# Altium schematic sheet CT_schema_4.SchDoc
size 349 x 342 mm
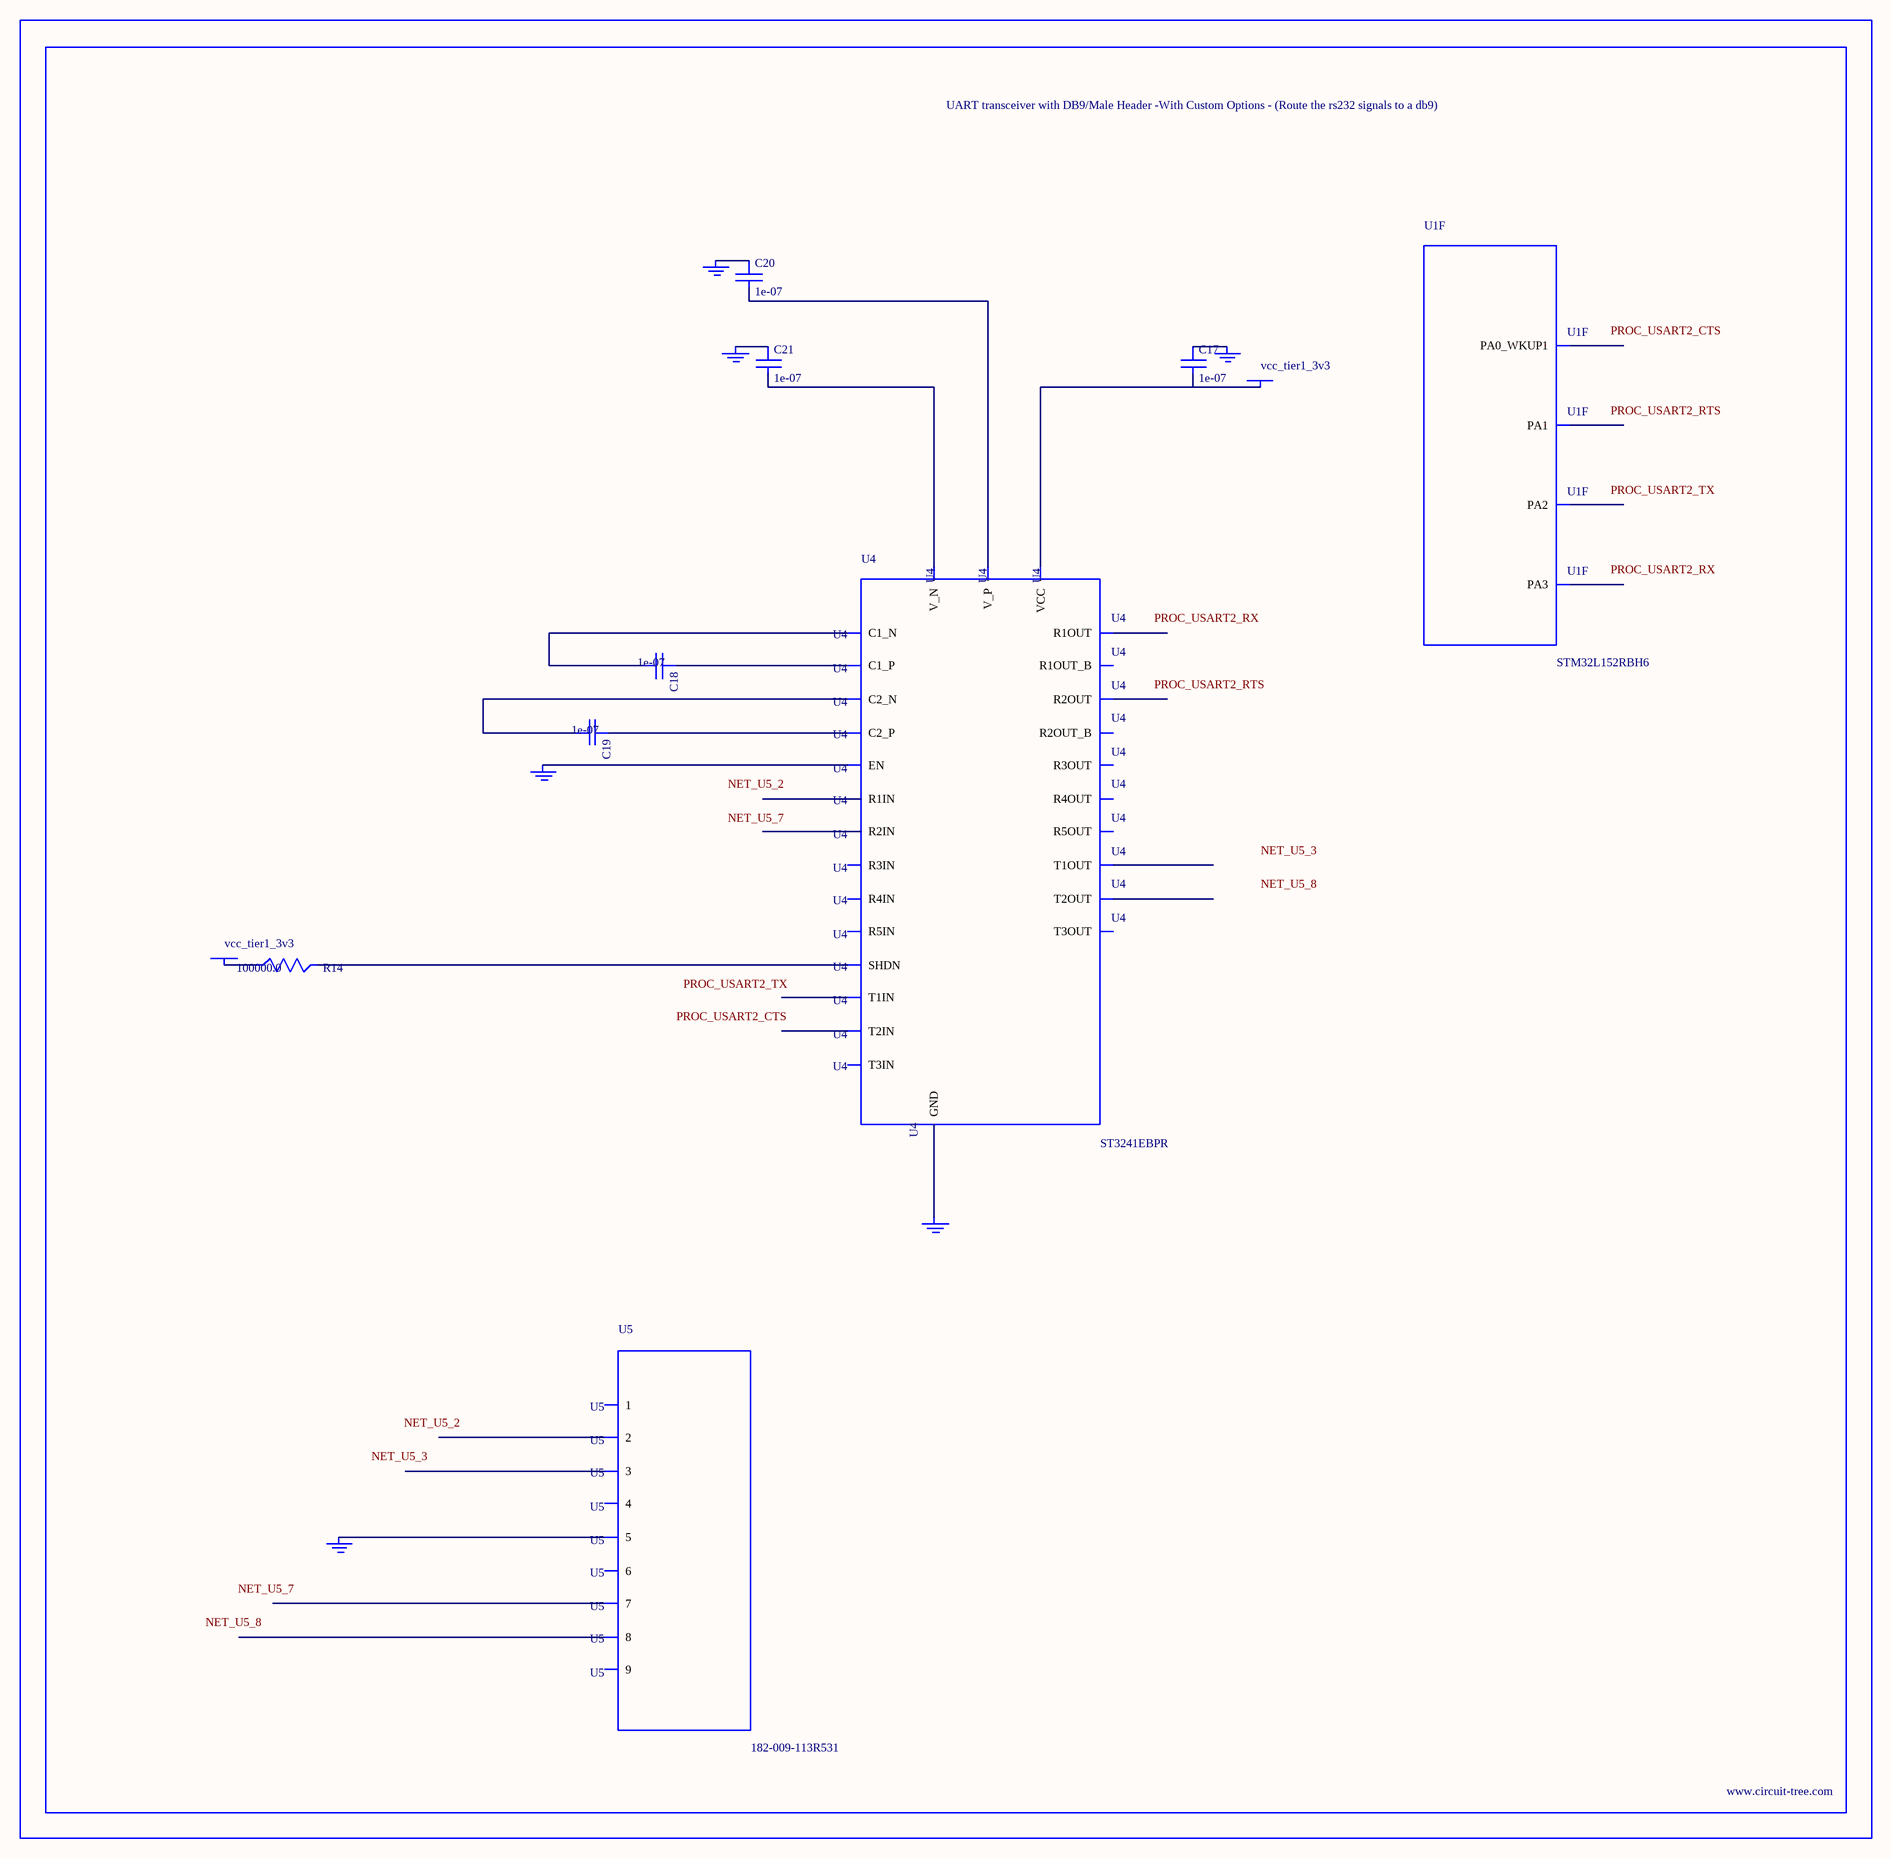
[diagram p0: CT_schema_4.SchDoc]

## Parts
BORDER3  (no value)
C17  1e-07  [C0402]
C18  1e-07  [C0402]
C19  1e-07  [C0402]
C20  1e-07  [C0402]
C21  1e-07  [C0402]
GND_INSTANCE_3_0  (no value)
GND_INSTANCE_3_1  (no value)
GND_INSTANCE_3_2  (no value)
GND_INSTANCE_3_3  (no value)
GND_INSTANCE_3_4  (no value)
GND_INSTANCE_3_5  (no value)
POWER_INSTANCE_3_0  vcc_tier1_3v3
POWER_INSTANCE_3_1  vcc_tier1_3v3
R14  100000.0  [R0603]
U1  STM32L152RBH6  [TFBGA64]  (part F of 7)
U4  ST3241EBPR  [SSOP-28]
U5  182-009-113R531  [182-009-MALE]

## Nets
NetC17_1: C17.1 GND_INSTANCE_3_2.0(GND)
NetC17_2: C17.2 POWER_INSTANCE_3_1.0(PWR) U4.26(VCC)
NetC18_1: C18.1 U4.28(C1_P)
NetC18_2: C18.2 U4.24(C1_N)
NetC19_1: C19.1 U4.1(C2_P)
NetC19_2: C19.2 U4.2(C2_N)
NetC20_1: C20.1 GND_INSTANCE_3_3.0(GND)
NetC20_2: C20.2 U4.27(V_P)
NetC21_1: C21.1 GND_INSTANCE_3_0.0(GND)
NetC21_2: C21.2 U4.3(V_N)
NetGND_INSTANCE_3_1_0: GND_INSTANCE_3_1.0(GND) U4.23(EN)
NetGND_INSTANCE_3_4_0: GND_INSTANCE_3_4.0(GND) U4.25(GND)
NetGND_INSTANCE_3_5_0: GND_INSTANCE_3_5.0(GND) U5.5
NetPOWER_INSTANCE_3_0_0: POWER_INSTANCE_3_0.0(PWR) R14.1
NetR14_2: R14.2 U4.22(SHDN)

Not connected (* = marked no-connect by the designer): U1 F3(PA2) G2(PA0_WKUP1) G3(PA3) H2(PA1); U4 4(R1IN) 5(R2IN) 6(R3IN) 7(R4IN) 8(R5IN) 9(T1OUT) 10(T2OUT) 11(T3OUT) 12(T3IN) 13(T2IN) 14(T1IN) 15(R5OUT) 16(R4OUT) 17(R3OUT) 18(R2OUT) 19(R1OUT) 20(R2OUT_B) 21(R1OUT_B); U5 1 2 3 4 6 7 8 9

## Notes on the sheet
- Labels drawn without touching a wire or pin: NET_U5_2, NET_U5_3, NET_U5_7, NET_U5_8, PROC_USART2_CTS, PROC_USART2_RTS, PROC_USART2_RX, PROC_USART2_TX

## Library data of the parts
BORDER3 = BORDER_PAGE3
C17-C21 = C0402C104K3RACTU
GND_INSTANCE_3_0-GND_INSTANCE_3_5 = GND
POWER_INSTANCE_3_0 POWER_INSTANCE_3_1 = PWR
R14 = RC0603JR-07100KL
